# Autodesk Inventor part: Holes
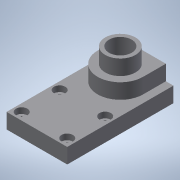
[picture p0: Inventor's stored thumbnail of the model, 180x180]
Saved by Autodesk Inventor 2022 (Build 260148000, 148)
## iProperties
Created: 2013-12
Part Number: Holes
Material: Generic
Document SubType Name: Modeling
Designer: John
Density: 1 g/cm^3
Appearance: Default
Author: John
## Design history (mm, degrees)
sketch "Sketch1"
  geometry: L1 (0, 0)-(-50.8, 0); L2 (-50.8, 0)-(-50.8, -88.9); L3 (-50.8, -88.9)-(0, -88.9); L4 (0, -88.9)-(0, 0)
  constraints: 8 end point, 2 parallel, 1 horizontal, 1 perpendicular
  dimensions: "d0" = 50.8 distance of L3.end L2.end; "d1" = 88.9 distance of L2.end L1.end
extrude "Extrusion1" new body sketch "Sketch1" distance "d2" = 12.7; taper "d3" = 0 deg
sketch "Sketch2"
  geometry: L1 (50.8, 0)-(50.8, 88.9) reference; L2 (50.8, 88.9)-(0, 88.9) reference; L3 (0, 88.9)-(0, 0) reference; L4 (6.35, 88.9)-(44.45, 88.9); L5 (44.45, 88.9)-(44.45, 69.85); L6 (44.45, 69.85)-(6.35, 69.85); L7 (6.35, 69.85)-(6.35, 88.9); L8 (6.35, 79.375)-(0, 79.375); L9 (44.45, 79.375)-(50.8, 79.375); 1 further point
  constraints: 12 end point, 3 midpoint, 3 perpendicular, 3 point on line, 2 parallel, 1 collinear, 1 horizontal, 1 horizontal alignment, 2 other
  dimensions: "d4" = 19.05 distance of L4.end L5.end; "d5" = 6.35 distance between parallel lines of L3 L7
extrude "Extrusion2" join sketch "Sketch2" distance "d6" = 12.7; taper "d7" = 0 deg
sketch "Sketch3"
  geometry: C1 r 12.7 at (25.4, 69.85); A1 r 19.05 centre (25.4, 69.85) between (6.35, 69.85) and (44.45, 69.85) reference; 1 further point
  constraints: 1 centre point, 1 coincident
  dimensions: "d8" = 25.4 diameter of C1
extrude "Extrusion3" join sketch "Sketch3" distance "d9" = 12.7; taper "d10" = 0 deg
sketch "Sketch6"
  geometry: L1 (0, 88.9)-(0, 0) reference; L2 (0, 0)-(50.8, 0) reference; L3 (50.8, 0)-(50.8, 88.9) reference; L4 (44.45, 88.9)-(44.45, 6.35); L5 (44.45, 6.35)-(6.35, 6.35); L6 (6.35, 6.35)-(6.35, 88.9); L7 (6.35, 38.1)-(44.45, 38.1)
  constraints: 8 end point, 2 point on line, 1 perpendicular, 2 other
  dimensions: "d35" = 6.35 distance between parallel lines of L2 L5; "d36" = 31.75 distance between parallel lines of L5 L7
hole "Hole3" diameter "d39" = 19.05; stored, may be unused: countersink angle "d43" = 82 deg, drill point angle "d45" = 118 deg; dims "d37" = 25.4, "d38" = 25.4, "d40" = 19.05, "d41" = 9.525, "d42" = 6.35, "d44" = 25.4
hole "Hole4" sketch "Sketch6" diameter "d46" = 5.1054; stored, may be unused: countersink angle "d50" = 82 deg, drill point angle "d52" = 118 deg; dims "d47" = 19.05, "d48" = 9.525, "d49" = 4.826, "d51" = 25.4
body "Solid1"
